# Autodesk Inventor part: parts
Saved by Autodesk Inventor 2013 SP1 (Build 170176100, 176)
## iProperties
Created: 2013-01
Part Number: parts
Material: Generic
Document SubType Name: Modeling
Designer: Kevin
Density: 1 g/cm^3
Author: Kevin
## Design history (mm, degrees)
node "parts1"
node "parts"
node "parts_1"
node "parts_2"
node "parts_3"
node "parts_4"
node "parts_5"
node "parts_6"
node "Base1"
node "Base2"
node "Base3"
node "Base4"
node "Base5"
node "Base6"
node "Base7"
